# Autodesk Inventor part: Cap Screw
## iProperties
Shininess: 77.0
Length Units: 11269
Angle Units: 11279
Time Units: 11290
Mass Units: 11283
Length Display Precision: 3
Angle Display Precision: 2
Created: 2002-02
Part Number: Cap Screw
Document SubType Name: Modeling
Designer: ***
Density: 1 g/cm^3
Density: 0.0
Volumn: 0.0
Area: 0.0
PropertySet Name: Model Information
Control State: 0
Master: False
Checked Out: False
Author: ***
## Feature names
1. Revolution1
2. Extrusion1
3. Extrusion2
